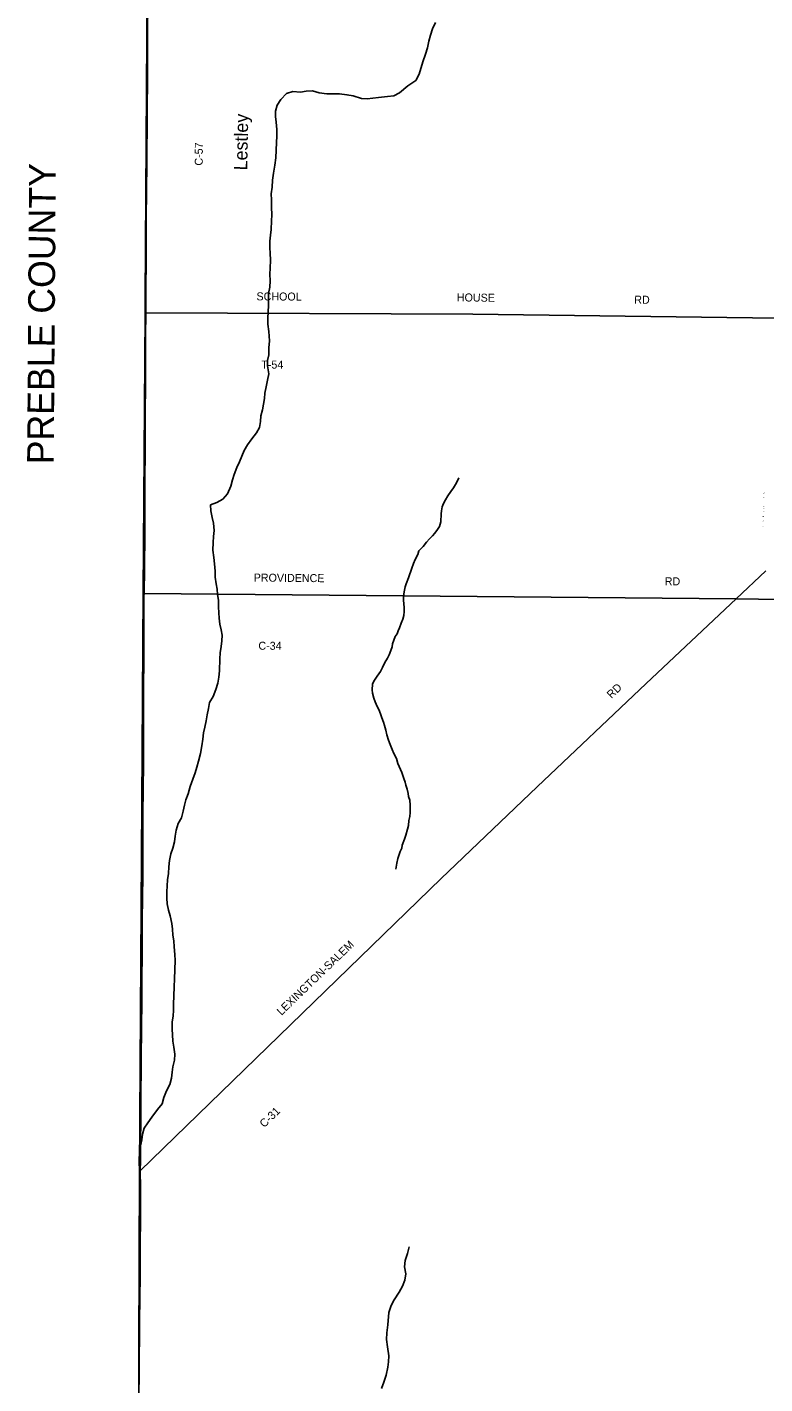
# Model space of a CAD drawing. Extents: x 1312308 to 1684953, y 460642 to 865172.
# Drawn here: x 1410332 to 1417251, y 657978 to 670697 of the extents above; entities that cross this region are included whole.
import ezdxf

# ---------------------------------------------------------------- set-up
doc = ezdxf.new("R2010")
doc.units = 0
for name, color, linetype in [('GM_X_Adjacent_County', 7, 'Continuous'), ('GM_X_Adjacent_County_Text', 7, 'Continuous'), ('GM_X_County', 7, 'Continuous'), ('GM_X_County_Road', 7, 'Continuous'), ('GM_X_County_Road_Text', 7, 'Continuous'), ('GM_X_Minor_River', 7, 'Continuous'), ('GM_X_Minor_River_Text', 7, 'Continuous'), ('GM_X_Township', 7, 'Continuous'), ('GM_X_Township_Road', 7, 'Continuous'), ('GM_X_Township_Road_Text', 7, 'Continuous'), ('GM_X_Township_Subdivision_Text', 7, 'Continuous')]:
    doc.layers.add(name, color=color, linetype=linetype)

msp = doc.modelspace()

# ---------------------------------------------------------------- linework, layer by layer
at = {"layer": 'GM_X_Adjacent_County'}
msp.add_lwpolyline([(1411554, 694026), (1411551, 688725), (1411547, 688368), (1411526, 683541), (1411498, 678086), (1411466, 675468), (1411467, 672788), (1411460, 671583), (1411440, 668150), (1411439, 668011), (1411421, 665395), (1411387, 659976), (1411378, 657454)], dxfattribs=at)
at = {"layer": 'GM_X_County'}
msp.add_lwpolyline([(1411378, 657454), (1411387, 659976), (1411421, 665395), (1411439, 668011), (1411440, 668150), (1411460, 671583), (1411467, 672788), (1411466, 675468), (1411498, 678086), (1411526, 683541), (1411547, 688368), (1411551, 688725), (1411554, 694026)], dxfattribs=at)
at = {"layer": 'GM_X_County_Road'}
for points in [[(1411393, 659976), (1411393, 659993), (1411394, 660054), (1411394, 660098), (1411395, 660165), (1411396, 660257), (1411397, 660431), (1411398, 660571), (1411400, 660731), (1411401, 660902), (1411403, 661114), (1411404, 661228), (1411405, 661334), (1411407, 661547), (1411407, 661625), (1411408, 661678), (1411409, 661822), (1411410, 661958), (1411410, 662077), (1411412, 662332), (1411413, 662524), (1411416, 662751), (1411416, 662900), (1411416, 662988), (1411417, 663297), (1411418, 663399), (1411419, 663470), (1411420, 663586), (1411422, 663764), (1411423, 663892), (1411424, 664074), (1411424, 664171), (1411424, 664251), (1411424, 664381), (1411425, 664544), (1411426, 664728), (1411427, 664863), (1411428, 664966), (1411428, 665049), (1411428, 665155), (1411428, 665228), (1411428, 665334), (1411428, 665363), (1411429, 665387), (1411429, 665401), (1411430, 665421), (1411430, 665450), (1411432, 665561), (1411434, 665746), (1411435, 665821), (1411437, 666130), (1411437, 666268), (1411437, 666387), (1411437, 666531), (1411438, 666639), (1411438, 666702), (1411438, 666814), (1411438, 666933), (1411439, 667024), (1411440, 667147), (1411441, 667275), (1411441, 667476), (1411442, 667620), (1411443, 667742), (1411443, 667826), (1411445, 667990), (1411445, 668019), (1411446, 668115), (1411446, 668149), (1411447, 668217), (1411447, 668332), (1411448, 668420), (1411448, 668551), (1411449, 668758), (1411450, 668971), (1411452, 669093), (1411452, 669209), (1411454, 669373), (1411455, 669545), (1411457, 669751), (1411458, 669864), (1411459, 669984), (1411461, 670147), (1411462, 670303), (1411462, 670410), (1411462, 670530), (1411462, 670690), (1411464, 670868)], [(1416981, 665337), (1417260, 665600)], [(1411393, 659976), (1414216, 662717), (1415117, 663575), (1416139, 664545), (1416981, 665337)], [(1411429, 665387), (1416981, 665337), (1417400, 665332), (1417576, 665329)], [(1411382, 657971), (1411383, 658026), (1411384, 658166), (1411386, 658480), (1411387, 658609), (1411389, 658738), (1411390, 658823), (1411391, 658951), (1411392, 659060), (1411393, 659166), (1411393, 659241), (1411393, 659305), (1411394, 659506), (1411395, 659700), (1411396, 659786), (1411396, 659841), (1411396, 659861), (1411396, 659875), (1411394, 659889), (1411393, 659907), (1411392, 659937), (1411393, 659976)]]:
    msp.add_lwpolyline(points, dxfattribs=at)
at = {"layer": 'GM_X_Minor_River'}
for points in [[(1412053, 666220), (1412112, 666242), (1412167, 666271), (1412211, 666322), (1412244, 666395), (1412259, 666453), (1412273, 666505), (1412299, 666569), (1412325, 666622), (1412345, 666676), (1412369, 666729), (1412398, 666781), (1412440, 666838), (1412482, 666893), (1412510, 666944), (1412520, 667001), (1412524, 667055), (1412539, 667109), (1412549, 667163), (1412557, 667217), (1412562, 667267), (1412574, 667325), (1412588, 667387), (1412598, 667447), (1412586, 667522), (1412586, 667572), (1412600, 667626), (1412600, 667692), (1412606, 667756), (1412598, 667843), (1412590, 667912), (1412590, 667968), (1412594, 668028), (1412596, 668089), (1412596, 668149), (1412597, 668201), (1412607, 668261), (1412611, 668320), (1412609, 668382), (1412611, 668438), (1412615, 668513), (1412613, 668577), (1412607, 668627), (1412609, 668692), (1412614, 668748), (1412620, 668800), (1412625, 668882), (1412626, 668939), (1412624, 669011), (1412623, 669078), (1412622, 669136), (1412630, 669198), (1412634, 669262), (1412642, 669328), (1412655, 669404), (1412665, 669472), (1412669, 669545), (1412671, 669617), (1412675, 669675), (1412675, 669738), (1412667, 669806), (1412663, 669861), (1412662, 669911), (1412676, 669965), (1412712, 670020), (1412764, 670075), (1412825, 670093), (1412895, 670087), (1412950, 670097), (1413010, 670099), (1413072, 670081), (1413142, 670071), (1413201, 670071), (1413263, 670072), (1413331, 670063), (1413391, 670052), (1413467, 670029), (1413521, 670025), (1413574, 670030), (1413628, 670038), (1413713, 670048), (1413770, 670052), (1413823, 670083), (1413904, 670146), (1413978, 670198), (1414010, 670258), (1414043, 670371), (1414068, 670443), (1414088, 670503), (1414100, 670567), (1414116, 670622), (1414135, 670680), (1414162, 670742)], [(1413791, 662805), (1413799, 662861), (1413808, 662905), (1413832, 662969), (1413846, 662999), (1413849, 663027), (1413870, 663084), (1413883, 663122), (1413901, 663178), (1413908, 663214), (1413913, 663260), (1413920, 663296), (1413923, 663334), (1413924, 663404), (1413920, 663449), (1413910, 663485), (1413905, 663513), (1413896, 663554), (1413885, 663590), (1413878, 663620), (1413866, 663653), (1413846, 663709), (1413835, 663738), (1413810, 663794), (1413797, 663841), (1413772, 663888), (1413755, 663926), (1413736, 663971), (1413721, 664013), (1413706, 664062), (1413695, 664108), (1413683, 664151), (1413673, 664183), (1413658, 664222), (1413647, 664260), (1413632, 664301), (1413615, 664329), (1413596, 664372), (1413583, 664408), (1413572, 664455), (1413567, 664485), (1413572, 664539), (1413585, 664567), (1413616, 664614), (1413647, 664658), (1413664, 664693), (1413687, 664741), (1413712, 664783), (1413727, 664814), (1413742, 664852), (1413755, 664888), (1413760, 664916), (1413785, 664984), (1413802, 665011), (1413811, 665039), (1413823, 665067), (1413840, 665109), (1413857, 665148), (1413864, 665182), (1413869, 665220), (1413868, 665255), (1413865, 665293), (1413862, 665323), (1413861, 665357), (1413868, 665403), (1413879, 665451), (1413888, 665479), (1413909, 665535), (1413941, 665624), (1413956, 665668), (1413973, 665708), (1413997, 665755), (1414007, 665789), (1414045, 665830), (1414078, 665870), (1414106, 665899), (1414135, 665927), (1414156, 665954), (1414181, 665988), (1414199, 666017), (1414213, 666061), (1414214, 666134), (1414217, 666162), (1414226, 666199), (1414237, 666233), (1414256, 666267), (1414277, 666303), (1414306, 666344), (1414330, 666378), (1414349, 666409), (1414366, 666437), (1414381, 666471)], [(1411382, 660097), (1411388, 660155), (1411396, 660209), (1411408, 660267), (1411415, 660319), (1411431, 660375), (1411463, 660426), (1411503, 660479), (1411555, 660552), (1411599, 660603), (1411615, 660663), (1411639, 660724), (1411671, 660784), (1411685, 660845), (1411693, 660901), (1411699, 660952), (1411715, 661013), (1411716, 661070), (1411708, 661134), (1411698, 661191), (1411694, 661249), (1411691, 661303), (1411691, 661368), (1411703, 661428), (1411705, 661478), (1411705, 661534), (1411710, 661699), (1411714, 661777), (1411719, 661948), (1411717, 662004), (1411711, 662075), (1411709, 662133), (1411700, 662184), (1411694, 662242), (1411688, 662294), (1411674, 662365), (1411657, 662418), (1411647, 662477), (1411641, 662533), (1411641, 662591), (1411644, 662646), (1411650, 662704), (1411658, 662762), (1411660, 662824), (1411668, 662886), (1411680, 662948), (1411700, 663000), (1411713, 663060), (1411721, 663112), (1411729, 663168), (1411749, 663232), (1411781, 663285), (1411795, 663347), (1411807, 663403), (1411822, 663455), (1411842, 663510), (1411860, 663580), (1411885, 663648), (1411907, 663706), (1411924, 663759), (1411940, 663815), (1411958, 663887), (1411971, 663959), (1411979, 664023), (1411987, 664083), (1411998, 664135), (1412010, 664195), (1412022, 664251), (1412034, 664309), (1412044, 664365), (1412078, 664422), (1412102, 664488), (1412120, 664546), (1412130, 664602), (1412136, 664664), (1412139, 664775), (1412143, 664833), (1412151, 664891), (1412158, 664943), (1412162, 664997), (1412151, 665048), (1412141, 665099), (1412133, 665157), (1412130, 665207), (1412128, 665264), (1412126, 665324), (1412119, 665377), (1412115, 665427), (1412104, 665478), (1412096, 665540), (1412096, 665597), (1412090, 665667), (1412082, 665726), (1412074, 665795), (1412076, 665867), (1412080, 665923), (1412086, 665977), (1412080, 666048), (1412069, 666101), (1412055, 666164), (1412053, 666220)], [(1411383, 660022), (1411382, 660097)], [(1413915, 659263), (1413901, 659199), (1413877, 659136), (1413871, 659074), (1413883, 659011), (1413875, 658949), (1413854, 658895), (1413820, 658838), (1413775, 658765), (1413747, 658714), (1413723, 658648), (1413716, 658532), (1413707, 658458), (1413703, 658394), (1413711, 658327), (1413723, 658240), (1413721, 658186), (1413715, 658134), (1413699, 658060), (1413677, 657995), (1413655, 657935)]]:
    msp.add_lwpolyline(points, dxfattribs=at)
at = {"layer": 'GM_X_Township'}
msp.add_lwpolyline([(1411378, 657454), (1411387, 659976), (1411421, 665395), (1411439, 668011), (1411440, 668150), (1411460, 671583), (1411467, 672788), (1414138, 672775), (1415014, 672778), (1415857, 672775), (1416556, 672769), (1417276, 672769), (1417662, 672772), (1419372, 672773), (1420996, 672758), (1422582, 672753), (1422900, 672752), (1424384, 672755), (1427419, 672761)], dxfattribs=at)
at = {"layer": 'GM_X_Township_Road'}
msp.add_lwpolyline([(1411445, 668019), (1414512, 668006), (1417610, 667967)], dxfattribs=at)

# ---------------------------------------------------------------- texts
at = {"layer": 'GM_X_Adjacent_County_Text'}
msp.add_text('PREBLE COUNTY', height=250, rotation=89.6123, dxfattribs=at).set_placement((1410582, 666598))
at = {"layer": 'GM_X_County_Road_Text'}
for s, rotation, p in [('C-57', 89.6662, (1411979, 669399)), ('PROVIDENCE', 359.4573, (1412457, 665500)), ('RD', 359.5064, (1416312, 665465)), ('C-34', 359.6558, (1412501, 664861)), ('RD', 43.6018, (1415812, 664399)), ('LEXINGTON-SALEM', 43.8748, (1412717, 661428)), ('C-31', 44.2752, (1412556, 660376))]:
    msp.add_text(s, height=75, rotation=rotation, dxfattribs=at).set_placement(p)
at = {"layer": 'GM_X_Minor_River_Text'}
msp.add_text('Lestley', height=125.1, rotation=88.8812, dxfattribs=at).set_placement((1412396, 669354))
at = {"layer": 'GM_X_Township_Road_Text'}
for s, rotation, p in [('SCHOOL', 359.6561, (1412483, 668136)), ('HOUSE', 359.2049, (1414362, 668127)), ('RD', 359.5064, (1416026, 668105)), ('T-54', 359.6465, (1412528, 667497))]:
    msp.add_text(s, height=75, rotation=rotation, dxfattribs=at).set_placement(p)
at = {"layer": 'GM_X_Township_Subdivision_Text'}
for s, rotation, p in [('T', 89.1257, (1417246, 666240)), ('N', 77.6976, (1417247, 666321)), ('L', 89.1257, (1417247, 666289)), ('R', 89.139, (1417245, 666143)), ('R', 89.1257, (1417244, 666104)), ('E', 89.1257, (1417246, 666205)), ('I', 89.126, (1417246, 666183)), ('H', 89.1256, (1417243, 666016)), ('A', 89.1256, (1417244, 666060))]:
    msp.add_text(s, height=12.5, rotation=rotation, dxfattribs=at).set_placement(p)

doc.saveas('drawing.dxf')
